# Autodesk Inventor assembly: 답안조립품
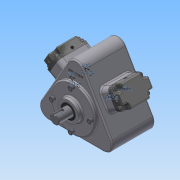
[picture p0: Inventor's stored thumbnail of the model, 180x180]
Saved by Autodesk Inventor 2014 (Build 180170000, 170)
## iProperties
Created: 2015-06
Part Number: 답안조립품
Document SubType Name: Assembly
Designer: Administrator
Mass: 5318.58 g
Surface Area: 2414.93 cm^2
Volume: 1564.62 cm^3
Density: 3.39928 g/cm^3
Author: Administrator
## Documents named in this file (20)
- C:\Users\Administrator\Desktop\350605V1038\답안조립품.iam
- C:\Users\Administrator\Desktop\350605V1038\본체.ipt
- C:\Users\Administrator\Desktop\350605V1038\베어링 NA 4904.ipt
- 베어링 NA 4904.ipt
- C:\Users\Administrator\Desktop\350605V1038\편심축.ipt
- C:\Users\Administrator\Desktop\350605V1038\앞커버.ipt
- C:\Users\Administrator\Desktop\350605V1038\M6x0.7x20.ipt
- M6x0.7x20.ipt
- C:\Users\Administrator\Desktop\350605V1038\부시.ipt
- C:\Users\Administrator\Desktop\350605V1038\슬라이드.ipt
- C:\Users\Administrator\Desktop\350605V1038\오일실.ipt
- 오일실.ipt
- C:\Users\Administrator\Desktop\350605V1038\헤더커버.ipt
- 헤더커버.ipt
- C:\Users\Administrator\Desktop\350605V1038\M4x0.5x16.ipt
- M4x0.5x16.ipt
- C:\Users\Administrator\Desktop\350605V1038\스프링1.ipt
- C:\Users\Administrator\Desktop\350605V1038\스프링2.ipt
- C:\Users\Administrator\Desktop\350605V1038\스프링3.ipt
- C:\Users\Administrator\Desktop\350605V1038\스프링4.ipt
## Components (14 placed, 3 different names)
1. M6x0.7x20:1
2. M6x0.7x20:2
3. M6x0.7x20:3
4. M6x0.7x20:4
5. 헤더커버:1
6. 헤더커버:2
7. M4x0.5x16:1
8. M4x0.5x16:2
9. M4x0.5x16:3
10. M4x0.5x16:4
11. M4x0.5x16:5
12. M4x0.5x16:6
13. M4x0.5x16:7
14. M4x0.5x16:8
